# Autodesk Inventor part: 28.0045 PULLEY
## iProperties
Created: 2006-12
Document SubType Name: Modeling
Designer: Andy Moles
Part Number: 28.0045 PULLEY
Material: Aluminum-6061
Mass: 364.841 g
Surface Area: 243.567 cm^2
Volume: 134.628 cm^3
Density: 2.71 g/cm^3
Author: Andy Moles
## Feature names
1. Extrusion1
2. Extrusion3
3. Extrusion4
4. Extrusion6
5. Mirror1
6. Extrusion7
